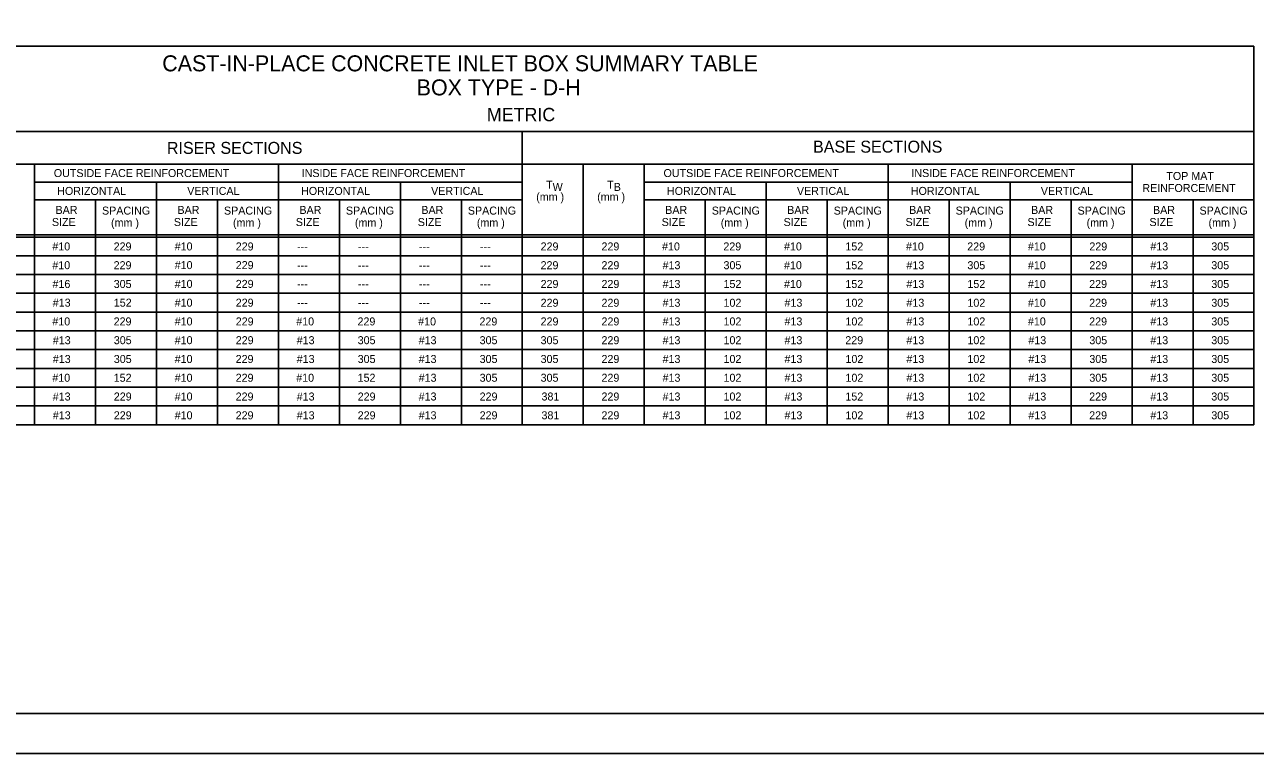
# Model space of a CAD drawing. Extents: x -6420 to 49575, y -4552 to 11624.
# Drawn here: x 40670 to 42184, y 3829 to 4726 of the extents above; entities that cross this region are included whole.
import ezdxf

# ---------------------------------------------------------------- set-up
doc = ezdxf.new("R2010")
doc.units = 0
doc.layers.add('1', color=7, linetype='Continuous')
doc.layers.add('4', color=7, linetype='Continuous')

msp = doc.modelspace()

# ---------------------------------------------------------------- linework, layer by layer
at = {"layer": '1'}
for p, q in [((42181.9, 4698.8), (40386.9, 4698.8)), ((42181.9, 4698.8), (42181.9, 4233.1)), ((42181.9, 4593.8), (40386.9, 4593.8)), ((41281.9, 4593.8), (41281.9, 4233.1)), ((42181.9, 4553.8), (40606.9, 4553.8)), ((40681.9, 4553.8), (40681.9, 4233.1)), ((40981.9, 4553.8), (40981.9, 4233.1)), ((41356.9, 4553.8), (41356.9, 4233.1)), ((41431.9, 4553.8), (41431.9, 4233.1)), ((41731.9, 4553.8), (41731.9, 4233.1)), ((42031.9, 4553.8), (42031.9, 4233.1)), ((40681.9, 4531.8), (40981.9, 4531.8)), ((40831.9, 4531.8), (40831.9, 4233.1)), ((40981.9, 4531.8), (41281.9, 4531.8)), ((41131.9, 4531.8), (41131.9, 4233.1)), ((41431.9, 4531.8), (41731.9, 4531.8)), ((41581.9, 4531.8), (41581.9, 4233.1)), ((41731.9, 4531.8), (42031.9, 4531.8)), ((41881.9, 4531.8), (41881.9, 4233.1)), ((40681.9, 4509.8), (40981.9, 4509.8)), ((40756.9, 4509.8), (40756.9, 4233.1)), ((40906.9, 4509.8), (40906.9, 4233.1)), ((40981.9, 4509.8), (41281.9, 4509.8)), ((41056.9, 4509.8), (41056.9, 4233.1)), ((41206.9, 4509.8), (41206.9, 4233.1)), ((41431.9, 4509.8), (41731.9, 4509.8)), ((41506.9, 4509.8), (41506.9, 4233.1)), ((41656.9, 4509.8), (41656.9, 4233.1)), ((41731.9, 4509.8), (42181.9, 4509.8)), ((41806.9, 4509.8), (41806.9, 4233.1)), ((41956.9, 4509.8), (41956.9, 4233.1)), ((42106.9, 4509.8), (42106.9, 4233.1)), ((40386.9, 4466.6), (42181.9, 4466.6)), ((40386.9, 4464.1), (42181.9, 4464.1)), ((40386.9, 4441), (42181.9, 4441)), ((40386.9, 4417.9), (42181.9, 4417.9)), ((40386.9, 4394.8), (42181.9, 4394.8)), ((40386.9, 4371.7), (42181.9, 4371.7)), ((40386.9, 4348.6), (42181.9, 4348.6)), ((40386.9, 4325.5), (42181.9, 4325.5)), ((40386.9, 4302.4), (42181.9, 4302.4)), ((40386.9, 4279.3), (42181.9, 4279.3)), ((40386.9, 4256.2), (42181.9, 4256.2)), ((40386.9, 4233.1), (42181.9, 4233.1))]:
    msp.add_line(p, q, dxfattribs=at)
msp.add_lwpolyline([(42890.7, 3877.8), (42890.7, 5728.2), (40311.9, 5728.2), (40311.9, 3877.8), (42890.7, 3877.8), (42890.7, 3964.3), (42234.5, 3964.3), (42234.5, 4176.5), (42890.7, 4176.5), (42890.7, 4271.5), (42234.5, 4271.5), (42234.5, 3877.8), (42493, 3877.8), (42493, 3964.3), (42493, 3877.8), (42745.6, 3877.8), (42745.6, 3964.3), (42745.6, 3923.9), (42890.7, 3923.9)], dxfattribs=at)
at = {"layer": '4'}
msp.add_lwpolyline([(40184, 5777.4), (42943.2, 5777.4), (42943.2, 3828.6), (40184, 3828.6)], close=True, dxfattribs=at)

# ---------------------------------------------------------------- texts
at = {"layer": '1'}
for s, height, p in [('CAST-IN-PLACE CONCRETE INLET BOX SUMMARY TABLE', 19.685, (40839, 4668)), ('BOX TYPE - D-H', 19.685, (41152, 4638.4)), ('METRIC', 16.4, (41238.3, 4606.6)), ('RISER SECTIONS', 14.764, (40844.7, 4566.4)), ('BASE SECTIONS', 14.764, (41639.5, 4567.9)), ('OUTSIDE FACE REINFORCEMENT', 9.843, (40705.6, 4537.9)), ('INSIDE FACE REINFORCEMENT', 9.843, (41010.5, 4537.9)), ('OUTSIDE FACE REINFORCEMENT', 9.843, (41455.6, 4537.9)), ('INSIDE FACE REINFORCEMENT', 9.843, (41760.5, 4537.9)), ('TOP MAT', 9.84, (42074.1, 4534.3)), ('T ', 9.84, (41311.2, 4523.5)), ('W', 9.84, (41319.2, 4520.8)), ('T ', 9.84, (41386.2, 4523.5)), ('B', 9.84, (41394.4, 4520.8)), ('REINFORCEMENT', 9.843, (42044.6, 4519.5)), ('HORIZONTAL', 9.84, (40709.8, 4515.9)), ('VERTICAL', 9.84, (40869.7, 4515.9)), ('HORIZONTAL', 9.84, (41009.8, 4515.9)), ('VERTICAL', 9.84, (41169.7, 4515.9)), ('(mm )', 9.84, (41299, 4508.7)), ('(mm )', 9.84, (41374, 4508.7)), ('HORIZONTAL', 9.84, (41459.8, 4515.9)), ('VERTICAL', 9.84, (41619.7, 4515.9)), ('HORIZONTAL', 9.84, (41759.8, 4515.9)), ('VERTICAL', 9.84, (41919.7, 4515.9)), ('BAR', 9.84, (40707.7, 4492.5)), ('SPACING', 9.84, (40764.9, 4491.7)), ('BAR', 9.84, (40857.7, 4492.5)), ('SPACING', 9.84, (40914.9, 4491.7)), ('BAR', 9.84, (41007.7, 4492.5)), ('SPACING', 9.84, (41064.9, 4491.7)), ('BAR', 9.84, (41157.7, 4492.5)), ('SPACING', 9.84, (41214.9, 4491.7)), ('BAR', 9.84, (41457.7, 4492.5)), ('SPACING', 9.84, (41514.9, 4491.7)), ('BAR', 9.84, (41607.7, 4492.5)), ('SPACING', 9.84, (41664.9, 4491.7)), ('BAR', 9.84, (41757.7, 4492.5)), ('SPACING', 9.84, (41814.9, 4491.7)), ('BAR', 9.84, (41907.7, 4492.5)), ('SPACING', 9.84, (41964.9, 4491.7)), ('BAR', 9.84, (42057.7, 4492.5)), ('SPACING', 9.84, (42114.9, 4491.7)), ('SIZE', 9.84, (40703.3, 4477.6)), ('(mm )', 9.84, (40776, 4476.9)), ('SIZE', 9.84, (40853.3, 4477.6)), ('(mm )', 9.84, (40926, 4476.9)), ('SIZE', 9.84, (41003.3, 4477.6)), ('(mm )', 9.84, (41076, 4476.9)), ('SIZE', 9.84, (41153.3, 4477.6)), ('(mm )', 9.84, (41226, 4476.9)), ('SIZE', 9.84, (41453.3, 4477.6)), ('(mm )', 9.84, (41526, 4476.9)), ('SIZE', 9.84, (41603.3, 4477.6)), ('(mm )', 9.84, (41676, 4476.9)), ('SIZE', 9.84, (41753.3, 4477.6)), ('(mm )', 9.84, (41826, 4476.9)), ('SIZE', 9.84, (41903.3, 4477.6)), ('(mm )', 9.84, (41976, 4476.9)), ('SIZE', 9.84, (42053.3, 4477.6)), ('(mm )', 9.84, (42126, 4476.9)), ('#10', 9.84, (40703.8, 4447.6)), ('229', 9.84, (40779.2, 4447.6)), ('#10', 9.84, (40854.3, 4447.6)), ('229', 9.84, (40929.4, 4447.6)), ('---', 9.84, (41004.8, 4447.6)), ('---', 9.84, (41079.8, 4447.6)), ('---', 9.84, (41154.8, 4447.6)), ('---', 9.84, (41229.8, 4447.6)), ('229', 9.84, (41304.4, 4447.6)), ('229', 9.84, (41379.3, 4447.6)), ('#10', 9.84, (41453.8, 4447.6)), ('229', 9.84, (41529.2, 4447.6)), ('#10', 9.84, (41603.8, 4447.6)), ('152', 9.84, (41679.3, 4447.6)), ('#10', 9.84, (41753.8, 4447.6)), ('229', 9.84, (41829.2, 4447.6)), ('#10', 9.84, (41903.8, 4447.6)), ('229', 9.84, (41979.4, 4447.6)), ('#13', 9.84, (42054.4, 4447.6)), ('305', 9.84, (42129.4, 4447.6)), ('#10', 9.84, (40703.8, 4424.5)), ('229', 9.84, (40779.2, 4424.5)), ('#10', 9.84, (40854.3, 4424.6)), ('229', 9.84, (40929.4, 4424.6)), ('---', 9.84, (41004.8, 4424.5)), ('---', 9.84, (41079.8, 4424.5)), ('---', 9.84, (41154.8, 4424.5)), ('---', 9.84, (41229.8, 4424.5)), ('229', 9.84, (41304.4, 4424.5)), ('229', 9.84, (41379.3, 4424.5)), ('#13', 9.84, (41454.4, 4424.5)), ('305', 9.84, (41529.4, 4424.5)), ('#10', 9.84, (41603.8, 4424.5)), ('152', 9.84, (41679.3, 4424.5)), ('#13', 9.84, (41754.4, 4424.5)), ('305', 9.84, (41829.4, 4424.5)), ('#10', 9.84, (41903.8, 4424.5)), ('229', 9.84, (41979.4, 4424.5)), ('#13', 9.84, (42054.4, 4424.5)), ('305', 9.84, (42129.4, 4424.5)), ('#16', 9.84, (40704, 4401.4)), ('305', 9.84, (40779.3, 4401.4)), ('#10', 9.84, (40854.3, 4401.5)), ('229', 9.84, (40929.4, 4401.5)), ('---', 9.84, (41004.8, 4401.4)), ('---', 9.84, (41079.8, 4401.4)), ('---', 9.84, (41154.8, 4401.4)), ('---', 9.84, (41229.8, 4401.4)), ('229', 9.84, (41304.4, 4401.4)), ('229', 9.84, (41379.3, 4401.4)), ('#13', 9.84, (41454.4, 4401.4)), ('152', 9.84, (41529.4, 4401.4)), ('#10', 9.84, (41603.8, 4401.4)), ('152', 9.84, (41679.3, 4401.4)), ('#13', 9.84, (41754.4, 4401.4)), ('152', 9.84, (41829.4, 4401.4)), ('#10', 9.84, (41903.8, 4401.4)), ('229', 9.84, (41979.2, 4401.4)), ('#13', 9.84, (42054.4, 4401.4)), ('305', 9.84, (42129.4, 4401.4)), ('#13', 9.84, (40704.3, 4378.4)), ('152', 9.84, (40779.4, 4378.4)), ('#10', 9.84, (40854.3, 4378.4)), ('229', 9.84, (40929.4, 4378.4)), ('---', 9.84, (41004.8, 4378.4)), ('---', 9.84, (41079.8, 4378.4)), ('---', 9.84, (41154.8, 4378.4)), ('---', 9.84, (41229.8, 4378.4)), ('229', 9.84, (41304.4, 4378.3)), ('229', 9.84, (41379.3, 4378.3)), ('#13', 9.84, (41454.4, 4378.3)), ('102', 9.84, (41529.4, 4378.3)), ('#13', 9.84, (41604.4, 4378.3)), ('102', 9.84, (41679.4, 4378.3)), ('#13', 9.84, (41754.4, 4378.3)), ('102', 9.84, (41829.4, 4378.3)), ('#10', 9.84, (41903.8, 4378.3)), ('229', 9.84, (41979.2, 4378.3)), ('#13', 9.84, (42054.4, 4378.3)), ('305', 9.84, (42129.4, 4378.3)), ('#10', 9.84, (40703.8, 4355.3)), ('229', 9.84, (40779.2, 4355.3)), ('#10', 9.84, (40854.3, 4355.3)), ('229', 9.84, (40929.4, 4355.3)), ('#10', 9.84, (41003.8, 4355.3)), ('229', 9.84, (41079.2, 4355.3)), ('#10', 9.84, (41153.8, 4355.3)), ('229', 9.84, (41229.2, 4355.3)), ('229', 9.84, (41304.4, 4355.3)), ('229', 9.84, (41379.3, 4355.3)), ('#13', 9.84, (41454.4, 4355.3)), ('102', 9.84, (41529.4, 4355.3)), ('#13', 9.84, (41604.4, 4355.3)), ('102', 9.84, (41679.4, 4355.3)), ('#13', 9.84, (41754.4, 4355.3)), ('102', 9.84, (41829.4, 4355.3)), ('#10', 9.84, (41903.8, 4355.3)), ('229', 9.84, (41979.2, 4355.3)), ('#13', 9.84, (42054.4, 4355.3)), ('305', 9.84, (42129.4, 4355.3)), ('#13', 9.84, (40704.4, 4332.2)), ('305', 9.84, (40779.4, 4332.2)), ('#10', 9.84, (40854.3, 4332.2)), ('229', 9.84, (40929.4, 4332.2)), ('#13', 9.84, (41004.4, 4332.2)), ('305', 9.84, (41079.4, 4332.2)), ('#13', 9.84, (41154.4, 4332.2)), ('305', 9.84, (41229.4, 4332.2)), ('305', 9.84, (41304.4, 4332.2)), ('229', 9.84, (41379.3, 4332.2)), ('#13', 9.84, (41454.4, 4332.2)), ('102', 9.84, (41529.4, 4332.2)), ('#13', 9.84, (41604.4, 4332.2)), ('229', 9.84, (41679.2, 4332.2)), ('#13', 9.84, (41754.4, 4332.2)), ('102', 9.84, (41829.4, 4332.2)), ('#13', 9.84, (41904.4, 4332.2)), ('305', 9.84, (41979.4, 4332.2)), ('#13', 9.84, (42054.4, 4332.2)), ('305', 9.84, (42129.4, 4332.2)), ('#13', 9.84, (40704.4, 4309.1)), ('305', 9.84, (40779.4, 4309.1)), ('#10', 9.84, (40854.3, 4309.1)), ('229', 9.84, (40929.3, 4309.1)), ('#13', 9.84, (41004.4, 4309.1)), ('305', 9.84, (41079.4, 4309.1)), ('#13', 9.84, (41154.4, 4309.1)), ('305', 9.84, (41229.4, 4309.1)), ('305', 9.84, (41304.4, 4309.1)), ('229', 9.84, (41379.3, 4309.1)), ('#13', 9.84, (41454.4, 4309.1)), ('102', 9.84, (41529.4, 4309.1)), ('#13', 9.84, (41604.4, 4309.1)), ('102', 9.84, (41679.4, 4309.1)), ('#13', 9.84, (41754.4, 4309.1)), ('102', 9.84, (41829.4, 4309.1)), ('#13', 9.84, (41904.4, 4309.1)), ('305', 9.84, (41979.4, 4309.1)), ('#13', 9.84, (42054.4, 4309.1)), ('305', 9.84, (42129.4, 4309.1)), ('#10', 9.84, (40703.8, 4286)), ('152', 9.84, (40779.3, 4286)), ('#10', 9.84, (40854.3, 4286)), ('229', 9.84, (40929.3, 4286)), ('#10', 9.84, (41003.8, 4286)), ('152', 9.84, (41079.3, 4286)), ('#13', 9.84, (41154.4, 4286)), ('305', 9.84, (41229.4, 4286)), ('305', 9.84, (41304.4, 4286)), ('229', 9.84, (41379.3, 4286)), ('#13', 9.84, (41454.4, 4286)), ('102', 9.84, (41529.4, 4286)), ('#13', 9.84, (41604.4, 4286)), ('102', 9.84, (41679.4, 4286)), ('#13', 9.84, (41754.4, 4286)), ('102', 9.84, (41829.4, 4286)), ('#13', 9.84, (41904.4, 4286)), ('305', 9.84, (41979.4, 4286)), ('#13', 9.84, (42054.4, 4286)), ('305', 9.84, (42129.4, 4286)), ('#13', 9.84, (40704.3, 4262.9)), ('229', 9.84, (40779.4, 4262.9)), ('#10', 9.84, (40854.3, 4262.9)), ('229', 9.84, (40929.3, 4262.9)), ('#13', 9.84, (41004.4, 4262.9)), ('229', 9.84, (41079.4, 4262.9)), ('#13', 9.84, (41154.4, 4262.9)), ('229', 9.84, (41229.4, 4262.9)), ('381', 9.84, (41305.5, 4262.9)), ('229', 9.84, (41379.3, 4262.9)), ('#13', 9.84, (41454.4, 4262.9)), ('102', 9.84, (41529.4, 4262.9)), ('#13', 9.84, (41604.4, 4262.9)), ('152', 9.84, (41679.3, 4262.9)), ('#13', 9.84, (41754.4, 4262.9)), ('102', 9.84, (41829.4, 4262.9)), ('#13', 9.84, (41904.4, 4262.9)), ('229', 9.84, (41979.2, 4262.9)), ('#13', 9.84, (42054.4, 4262.9)), ('305', 9.84, (42129.4, 4262.9)), ('#13', 9.84, (40704.4, 4239.8)), ('229', 9.84, (40779.4, 4239.8)), ('#10', 9.84, (40854.3, 4239.8)), ('229', 9.84, (40929.3, 4239.8)), ('#13', 9.84, (41004.4, 4239.8)), ('229', 9.84, (41079.4, 4239.8)), ('#13', 9.84, (41154.4, 4239.8)), ('229', 9.84, (41229.4, 4239.8)), ('381', 9.84, (41305.5, 4239.8)), ('229', 9.84, (41379.3, 4239.8)), ('#13', 9.84, (41454.4, 4239.8)), ('102', 9.84, (41529.4, 4239.8)), ('#13', 9.84, (41604.4, 4239.8)), ('102', 9.84, (41679.4, 4239.8)), ('#13', 9.84, (41754.4, 4239.8)), ('102', 9.84, (41829.4, 4239.8)), ('#13', 9.84, (41904.4, 4239.8)), ('229', 9.84, (41979.2, 4239.8)), ('#13', 9.84, (42054.4, 4239.8)), ('305', 9.84, (42129.4, 4239.8))]:
    msp.add_text(s, height=height, dxfattribs=at).set_placement(p)

doc.saveas('drawing.dxf')
